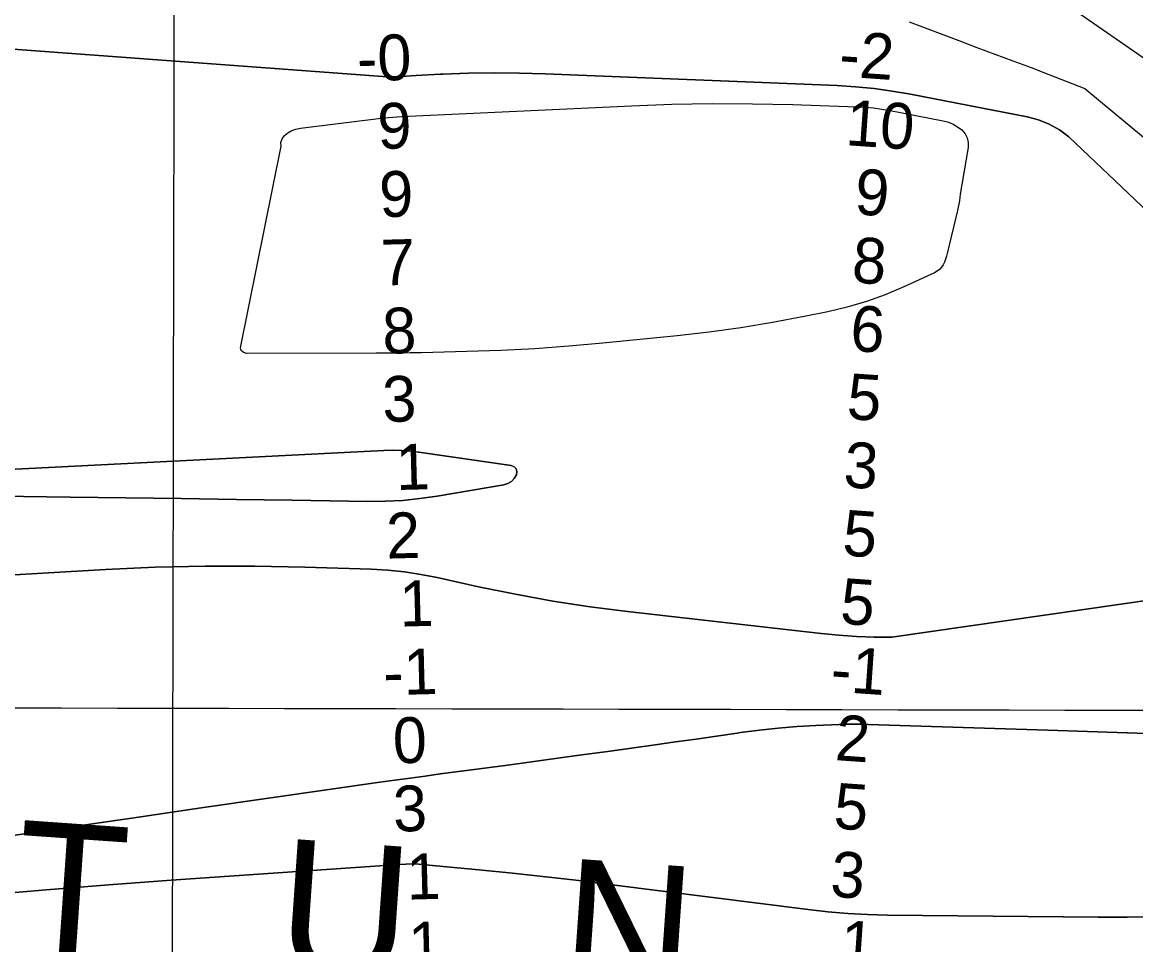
# Model space of a CAD drawing. Extents: x 3192986 to 3230865, y 867483 to 892886.
# Drawn here: x 3207434 to 3209065, y 878614 to 879965 of the extents above; entities that cross this region are included whole.
import ezdxf

# ---------------------------------------------------------------- set-up
doc = ezdxf.new("R2010")
doc.units = 0
for name, color, linetype in [('V-GRID-MAJR', 7, 'Continuous'), ('V-RIVR-IDEN', 7, 'Continuous'), ('V-RIVR-RANG', 7, 'Continuous'), ('V-TOPO-DPTH', 7, 'Continuous'), ('V-TOPO-MINR', 7, 'Continuous')]:
    doc.layers.add(name, color=color, linetype=linetype)

msp = doc.modelspace()

# ---------------------------------------------------------------- linework, layer by layer
at = {"layer": 'V-GRID-MAJR'}
for points in [[(3207642.5, 872901.1), (3207654.8, 878960.7), (3207667.2, 885023.3), (3207679.5, 891086), (3207679.5, 891089.1)], [(3197200.8, 878983.5), (3202427.8, 878971.7), (3207654.8, 878960.7), (3212881.9, 878950.4), (3218108.9, 878940.9), (3223335.9, 878932.2), (3228562.9, 878924.2)]]:
    msp.add_spline(points, degree=3, dxfattribs=at)
at = {"layer": 'V-TOPO-DPTH'}
for points in [[(3208717.5, 880162), (3209341.4, 879729.9)], [(3208717.5, 880162), (3209341.4, 879729.9)], [(3209287.9, 879492.7), (3208967.2, 879797.3), (3208953.3, 879807.4), (3208938.6, 879815.9), (3208922.8, 879822.1), (3208906.3, 879826.6), (3208735.2, 879859.8), (3208708.6, 879864.3), (3208681.8, 879868.1), (3208654.9, 879870.6), (3208627.9, 879872.3), (3208200.2, 879889.7), (3208162.6, 879890.7), (3208125.1, 879891.1), (3208087.6, 879890.4), (3208050.1, 879889.1), (3208046.9, 879889), (3208011.1, 879887), (3207975.2, 879884.8), (3207090.3, 879950.2)], [(3209287.9, 879492.7), (3208967.2, 879797.3), (3208953.3, 879807.4), (3208938.6, 879815.9), (3208922.8, 879822.1), (3208906.3, 879826.6), (3208735.2, 879859.8), (3208708.6, 879864.3), (3208681.8, 879868.1), (3208654.9, 879870.6), (3208627.9, 879872.3), (3208200.2, 879889.7), (3208162.6, 879890.7), (3208125.1, 879891.1), (3208087.6, 879890.4), (3208050.1, 879889.1), (3208046.9, 879889), (3208011.1, 879887), (3207975.2, 879884.8), (3207090.3, 879950.2)], [(3208150.6, 879292.8), (3208154.7, 879297.1), (3208158.1, 879302.3), (3208158.6, 879307.1), (3208157.7, 879311.2), (3208154.7, 879314.1), (3208150.4, 879316.3), (3208014.8, 879335.8), (3208002.1, 879337.2), (3207989.4, 879338.2), (3207976.6, 879338.4), (3207963.8, 879338.1), (3207231.3, 879301.1)], [(3207231.3, 879301.1), (3207963.8, 879338.1), (3207976.6, 879338.4), (3207989.4, 879338.2), (3208002.1, 879337.2), (3208014.8, 879335.8), (3208150.4, 879316.3), (3208154.7, 879314.1), (3208157.7, 879311.2), (3208158.6, 879307.1), (3208158.1, 879302.3), (3208154.7, 879297.1), (3208150.6, 879292.8)], [(3207093.8, 879275.5), (3207504.4, 879269.9), (3207585.6, 879268.8), (3207666.7, 879267.6), (3207747.9, 879266.4), (3207829.1, 879265.2), (3207940.3, 879263.5), (3207965.8, 879263.8), (3207991.3, 879265), (3208016.6, 879267.7), (3208041.9, 879271.3), (3208139.5, 879287.9), (3208145.4, 879289.9), (3208150.6, 879292.8)], [(3208150.6, 879292.8), (3208145.4, 879289.9), (3208139.5, 879287.9), (3208041.9, 879271.3), (3208016.6, 879267.7), (3207991.3, 879265), (3207965.8, 879263.8), (3207940.3, 879263.5), (3207829.1, 879265.2), (3207747.9, 879266.4), (3207666.7, 879267.6), (3207585.6, 879268.8), (3207504.4, 879269.9), (3207093.8, 879275.5)], [(3207121.1, 879138.4), (3207556, 879163.7), (3207628.9, 879167), (3207701.9, 879168.9), (3207774.9, 879168.8), (3207848, 879167.4), (3207945.3, 879164.2), (3207969.6, 879162.7), (3207993.8, 879160.4), (3208017.8, 879156.7), (3208041.7, 879152.1), (3208102.4, 879138.6), (3208156.7, 879127.5), (3208211.1, 879117.6), (3208265.9, 879109.3), (3208320.9, 879102.2), (3208604.6, 879070.3), (3208630.4, 879067.8), (3208656.3, 879065.9), (3208682.2, 879064.9), (3208708.1, 879064.5), (3209209.4, 879136.8)], [(3207121.1, 879138.4), (3207556, 879163.7), (3207628.9, 879167), (3207701.9, 879168.9), (3207774.9, 879168.8), (3207848, 879167.4), (3207945.3, 879164.2), (3207969.6, 879162.7), (3207993.8, 879160.4), (3208017.8, 879156.7), (3208041.7, 879152.1), (3208102.4, 879138.6), (3208156.7, 879127.5), (3208211.1, 879117.6), (3208265.9, 879109.3), (3208320.9, 879102.2), (3208604.6, 879070.3), (3208630.4, 879067.8), (3208656.3, 879065.9), (3208682.2, 879064.9), (3208708.1, 879064.5), (3209209.4, 879136.8)], [(3209111, 878922.9), (3209052.7, 878924.8), (3208994.5, 878926.7), (3208936.2, 878928.6), (3208673.4, 878937), (3208662.8, 878937.2), (3208652.1, 878937.3), (3208641.5, 878937.1), (3208630.9, 878936.8), (3208596.7, 878935.3), (3208569, 878933.7), (3208541.4, 878931.5), (3208513.9, 878928.5), (3208486.4, 878924.9), (3208481.2, 878924.2), (3208451.2, 878919.9), (3208421.1, 878915.6), (3208391, 878911.4), (3208361, 878907.1), (3208295.5, 878898), (3208246.6, 878891.2), (3208197.7, 878884.5), (3208148.8, 878877.9), (3208099.9, 878871.4), (3208046.3, 878864.4), (3208024.2, 878861.4), (3208002.1, 878858.4), (3207980, 878855.4), (3207957.9, 878852.3), (3207798.2, 878829.4), (3207696.3, 878814.7), (3207594.4, 878799.9), (3207492.5, 878784.9), (3207390.7, 878769.7)], [(3209111, 878922.9), (3209052.7, 878924.8), (3208994.5, 878926.7), (3208936.2, 878928.6), (3208673.4, 878937), (3208662.8, 878937.2), (3208652.1, 878937.3), (3208641.5, 878937.1), (3208630.9, 878936.8), (3208596.7, 878935.3), (3208569, 878933.7), (3208541.4, 878931.5), (3208513.9, 878928.5), (3208486.4, 878924.9), (3208481.2, 878924.2), (3208451.2, 878919.9), (3208421.1, 878915.6), (3208391, 878911.4), (3208361, 878907.1), (3208295.5, 878898), (3208246.6, 878891.2), (3208197.7, 878884.5), (3208148.8, 878877.9), (3208099.9, 878871.4), (3208046.3, 878864.4), (3208024.2, 878861.4), (3208002.1, 878858.4), (3207980, 878855.4), (3207957.9, 878852.3), (3207798.2, 878829.4), (3207696.3, 878814.7), (3207594.4, 878799.9), (3207492.5, 878784.9), (3207390.7, 878769.7)], [(3207377.8, 878686.8), (3207469.2, 878694.8), (3207560.7, 878702), (3207652.2, 878708.8), (3207986, 878732), (3207995.7, 878732.4), (3208005.3, 878732.6), (3208015, 878732.2), (3208024.6, 878731.5), (3208103.1, 878724.1), (3208152, 878719.2), (3208200.8, 878714), (3208249.6, 878708.3), (3208298.3, 878702.3), (3208585.4, 878665.7), (3208614.3, 878662.5), (3208643.3, 878660), (3208672.3, 878658.6), (3208701.4, 878657.8), (3209010.3, 878654.8), (3209052.6, 878654.8), (3209094.9, 878655.1)], [(3207377.8, 878686.8), (3207469.2, 878694.8), (3207560.7, 878702), (3207652.2, 878708.8), (3207986, 878732), (3207995.7, 878732.4), (3208005.3, 878732.6), (3208015, 878732.2), (3208024.6, 878731.5), (3208103.1, 878724.1), (3208152, 878719.2), (3208200.8, 878714), (3208249.6, 878708.3), (3208298.3, 878702.3), (3208585.4, 878665.7), (3208614.3, 878662.5), (3208643.3, 878660), (3208672.3, 878658.6), (3208701.4, 878657.8), (3209010.3, 878654.8), (3209052.6, 878654.8), (3209094.9, 878655.1)]]:
    msp.add_lwpolyline(points, dxfattribs=at)
at = {"layer": 'V-TOPO-MINR'}
for points in [[(3208717.5, 880162), (3209341.4, 879729.9)], [(3208733.1, 879965.7), (3208806.2, 879938.3), (3208832.6, 879928.4), (3208859, 879918.5), (3208885.4, 879908.6), (3208911.8, 879898.8), (3208938.1, 879888.8), (3208964.4, 879878.6), (3208990.6, 879868.2), (3209268.4, 879637.8)], [(3207090.3, 879950.2), (3207975.2, 879884.8), (3208011.1, 879887), (3208046.9, 879889), (3208050.1, 879889.1), (3208087.6, 879890.4), (3208125.1, 879891.1), (3208162.6, 879890.7), (3208200.2, 879889.7), (3208627.9, 879872.3), (3208654.9, 879870.6), (3208681.8, 879868.1), (3208708.6, 879864.3), (3208735.2, 879859.8), (3208906.3, 879826.6), (3208922.8, 879822.1), (3208938.6, 879815.9), (3208953.3, 879807.4), (3208967.2, 879797.3), (3209287.9, 879492.7)], [(3208797.8, 879815.9), (3208804.3, 879812.1), (3208810.5, 879807.5), (3208815.1, 879801.9), (3208818.4, 879795.9), (3208819.7, 879789.1), (3208819.6, 879781.8), (3208810.5, 879727.7), (3208809.7, 879722.9), (3208809, 879718.1), (3208808.2, 879713.3), (3208807.6, 879708.5), (3208806.9, 879703.7), (3208806.1, 879698.9), (3208805.1, 879694.2), (3208804.1, 879689.4), (3208789.2, 879626.7), (3208788, 879622.4), (3208786.6, 879618.1), (3208784.9, 879614), (3208782.9, 879610), (3208780.5, 879606.4), (3208777.7, 879603.2), (3208774.4, 879600.6), (3208770.6, 879598.4), (3208725.3, 879577.6), (3208698.3, 879566.2), (3208670.8, 879556.2), (3208642.7, 879548.1), (3208614.2, 879541.3), (3208579.5, 879534.2), (3208533.3, 879525.6), (3208486.8, 879517.8), (3208440.2, 879511.5), (3208393.4, 879506.1), (3208284.3, 879495.1), (3208234.7, 879490.7), (3208185, 879487), (3208135.2, 879484.5), (3208085.4, 879482.8), (3208019, 879481.2), (3208002.4, 879480.9), (3207985.7, 879480.7), (3207969.1, 879480.5), (3207952.5, 879480.4), (3207762.4, 879480.1), (3207757.9, 879481.8), (3207754.8, 879484.4), (3207753.9, 879488.3), (3207813.4, 879783.9), (3207812.9, 879789.2), (3207814.7, 879794.3), (3207818, 879799.2), (3207823.2, 879803.3), (3207828.8, 879806.6), (3207835, 879808.8), (3207841.5, 879810.2), (3207963.9, 879825), (3207970.3, 879825.7), (3207976.7, 879826.3), (3207983.1, 879826.8), (3207989.6, 879827.1), (3208326.5, 879843), (3208385.6, 879845.1), (3208444.7, 879846.2), (3208503.8, 879845.8), (3208562.9, 879844.6), (3208656.5, 879841.4), (3208668.8, 879840.7), (3208681, 879839.6), (3208693.2, 879838), (3208705.3, 879835.9), (3208783.3, 879820.8), (3208790.7, 879818.7), (3208797.8, 879815.9)], [(3208150.6, 879292.8), (3208154.7, 879297.1), (3208158.1, 879302.3), (3208158.6, 879307.1), (3208157.7, 879311.2), (3208154.7, 879314.1), (3208150.4, 879316.3), (3208014.8, 879335.8), (3208002.1, 879337.2), (3207989.4, 879338.2), (3207976.6, 879338.4), (3207963.8, 879338.1), (3207231.3, 879301.1)], [(3207093.8, 879275.5), (3207504.4, 879269.9), (3207585.6, 879268.8), (3207666.7, 879267.6), (3207747.9, 879266.4), (3207829.1, 879265.2), (3207940.3, 879263.5), (3207965.8, 879263.8), (3207991.3, 879265), (3208016.6, 879267.7), (3208041.9, 879271.3), (3208139.5, 879287.9), (3208145.4, 879289.9), (3208150.6, 879292.8)], [(3209209.4, 879136.8), (3208708.1, 879064.5), (3208682.2, 879064.9), (3208656.3, 879065.9), (3208630.4, 879067.8), (3208604.6, 879070.3), (3208320.9, 879102.2), (3208265.9, 879109.3), (3208211.1, 879117.6), (3208156.7, 879127.5), (3208102.4, 879138.6), (3208041.7, 879152.1), (3208017.8, 879156.7), (3207993.8, 879160.4), (3207969.6, 879162.7), (3207945.3, 879164.2), (3207848, 879167.4), (3207774.9, 879168.8), (3207701.9, 879168.9), (3207628.9, 879167), (3207556, 879163.7), (3207121.1, 879138.4)], [(3207390.7, 878769.7), (3207492.5, 878784.9), (3207594.4, 878799.9), (3207696.3, 878814.7), (3207798.2, 878829.4), (3207957.9, 878852.3), (3207980, 878855.4), (3208002.1, 878858.4), (3208024.2, 878861.4), (3208046.3, 878864.4), (3208099.9, 878871.4), (3208148.8, 878877.9), (3208197.7, 878884.5), (3208246.6, 878891.2), (3208295.5, 878898), (3208361, 878907.1), (3208391, 878911.4), (3208421.1, 878915.6), (3208451.2, 878919.9), (3208481.2, 878924.2), (3208486.4, 878924.9), (3208513.9, 878928.5), (3208541.4, 878931.5), (3208569, 878933.7), (3208596.7, 878935.3), (3208630.9, 878936.8), (3208641.5, 878937.1), (3208652.1, 878937.3), (3208662.8, 878937.2), (3208673.4, 878937), (3208936.2, 878928.6), (3208994.5, 878926.7), (3209052.7, 878924.8), (3209111, 878922.9)], [(3209094.9, 878655.1), (3209052.6, 878654.8), (3209010.3, 878654.8), (3208701.4, 878657.8), (3208672.3, 878658.6), (3208643.3, 878660), (3208614.3, 878662.5), (3208585.4, 878665.7), (3208298.3, 878702.3), (3208249.6, 878708.3), (3208200.8, 878714), (3208152, 878719.2), (3208103.1, 878724.1), (3208024.6, 878731.5), (3208015, 878732.2), (3208005.3, 878732.6), (3207995.7, 878732.4), (3207986, 878732), (3207652.2, 878708.8), (3207560.7, 878702), (3207469.2, 878694.8), (3207377.8, 878686.8)]]:
    msp.add_lwpolyline(points, dxfattribs=at)

# ---------------------------------------------------------------- texts
at = {"layer": 'V-RIVR-IDEN'}
msp.add_text('T   U   N   ', height=200, rotation=355.9975, dxfattribs=at).set_placement((3207417.9, 878597.6))
at = {"layer": 'V-RIVR-RANG'}
for s, rotation, p in [('-0', 1.5181, (3207925.2, 879878.8)), ('-2', 356, (3208629.3, 879886.1)), ('9', 1.5181, (3207955.2, 879779.5)), ('10', 356, (3208639, 879785.3)), ('9', 1.5181, (3207957.8, 879679.6)), ('9', 356, (3208652.1, 879684.2)), ('7', 1.5181, (3207960.2, 879579.6)), ('8', 356, (3208648.1, 879584.3)), ('8', 1.5181, (3207962.3, 879479.6)), ('6', 356, (3208645.5, 879484.3)), ('3', 1.5181, (3207962.3, 879379.6)), ('5', 356, (3208640.7, 879384.5)), ('3', 356, (3208635.9, 879284.6)), ('1', 1.5181, (3207982, 879280.1)), ('5', 356, (3208634.3, 879184.6)), ('2', 1.5181, (3207968, 879179.7)), ('1', 1.5181, (3207987.3, 879080.1)), ('5', 356, (3208631, 879084.6)), ('-1', 1.5181, (3207963.5, 878979.5)), ('-1', 356, (3208617, 878985.4)), ('0', 1.5181, (3207977.7, 878879.8)), ('2', 356, (3208623.6, 878884.8)), ('3', 1.5181, (3207978, 878779.8)), ('5', 356, (3208621.4, 878784.8)), ('1', 1.5181, (3207997.7, 878680.3)), ('3', 356, (3208616.6, 878684.9)), ('1', 1.5181, (3208000.4, 878580.3)), ('1', 356, (3208630.5, 878583.8))]:
    msp.add_text(s, height=67, rotation=rotation, dxfattribs=at).set_placement(p)

doc.saveas('drawing.dxf')
